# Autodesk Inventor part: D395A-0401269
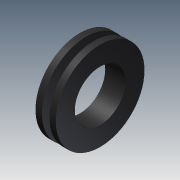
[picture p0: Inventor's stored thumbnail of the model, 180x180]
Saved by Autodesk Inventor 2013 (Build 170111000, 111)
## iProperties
Shininess: 69.0
Length Units: 11269
Angle Units: 11279
Time Units: 11290
Mass Units: 11283
Length Display Precision: 3
Angle Display Precision: 2
Created: 2002-06
Part Number: D395A-0401269
Material: Rubber
Document SubType Name: Modeling
Designer: LAlexey
Density: 0.93 g/cm^3
Mass: 3.61777 g
Surface Area: 34.5575 cm^2
Volume: 3.89008 cm^3
Density: 1.06
Volumn: 3.8900771033075623
Area: 34.55751918948772
PropertySet Name: Model Information
Control State: 0
Master: False
Checked Out: True
Checked Out Date: 2008-10-15
Last Check In Date: 2008-10-15
Author: LAlexey
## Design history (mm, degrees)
body "Solid1"
revolve "Revolution1" stored, may be unused: angle "d6" = 90 deg
sketch "Sketch1"
  geometry: L1 (0.27, 33.081)-(0.27, 40.581); L2 (0.27, 40.581)-(2.77, 40.581); L3 (2.77, 40.581)-(2.77, 36.081); L4 (2.77, 36.081)-(5.77, 36.081); L5 (5.77, 36.081)-(5.77, 40.581); L6 (5.77, 40.581)-(8.27, 40.581); L7 (8.27, 40.581)-(8.27, 33.081); L8 (8.27, 33.081)-(0.27, 33.081); L9 (6.357, 23.081)-(8.857, 23.081)
  constraints: 18 end point, 6 parallel, 2 equal length, 1 collinear, 1 perpendicular, 1 vertical
  dimensions: "d0" = 3 distance between parallel lines of L5 L3; "d1" = 10 distance between parallel lines of L9 L8; "d2" = 13 distance between parallel lines of L9 L4; "d3" = 0 distance between parallel lines of L6 L2; "d4" = 8 distance between parallel lines of L7 L1; "d5" = 17.5 distance between parallel lines of L9 L6
